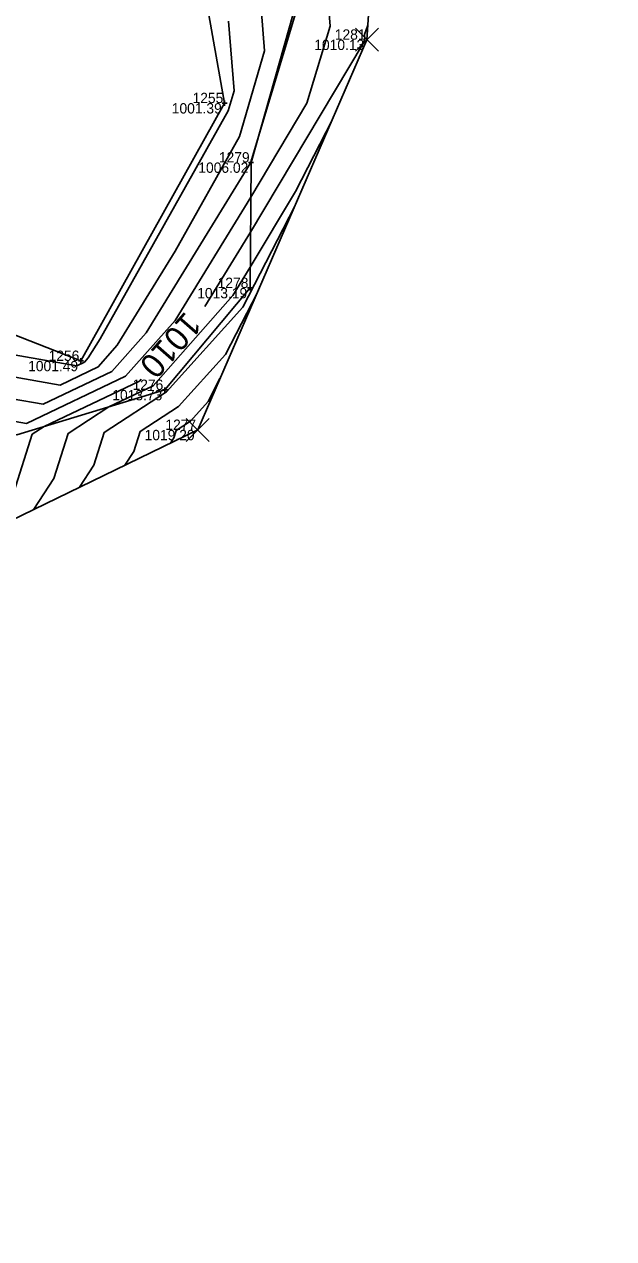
# Model space of a CAD drawing. Extents: x 2354693 to 2355622, y 637071 to 710080.
# Drawn here: x 2355546 to 2355614.4, y 709334.6 to 709475.6 of the extents above; entities that cross this region are included whole.
import ezdxf

# ---------------------------------------------------------------- set-up
doc = ezdxf.new("R2010")
doc.units = 0
for name, color, linetype in [('Default', 7, 'Continuous'), ('DT_X_Contour_Major', 7, 'Continuous'), ('DT_X_Contour_Minor', 7, 'Continuous'), ('HY_X_Water_Edge', 7, 'Continuous'), ('SV_X_Random_Point', 7, 'Continuous'), ('SV_X_Shot_Marker', 7, 'Continuous'), ('SV_X_Text_Elevation', 7, 'Continuous'), ('SV_X_Text_Name', 7, 'Continuous'), ('SV_X_Toe_of_Slope', 7, 'Continuous'), ('SV_X_Top_of_Bank', 7, 'Continuous')]:
    doc.layers.add(name, color=color, linetype=linetype)

msp = doc.modelspace()

# ---------------------------------------------------------------- linework, layer by layer
at = {"layer": 'Default'}
msp.add_lwpolyline([(2355263.76, 708986.4), (2355330.91, 709003.61), (2355347.35, 709002.09), (2355387.45, 709051.54), (2355402.1, 709089.16), (2355425.96, 709130.16), (2355495.56, 709194.41), (2355530.33, 709221.46), (2355525, 709302.12), (2355509.66, 709318.33), (2355534.8, 709413.26), (2355566.11, 709428.47), (2355585.74, 709473.78), (2355589.64, 709532.44), (2355608.23, 709591.27)], dxfattribs=at)
msp.add_lwpolyline([(2355263.76, 708986.4), (2355330.91, 709003.61), (2355347.35, 709002.09), (2355387.45, 709051.54), (2355402.1, 709089.16), (2355425.96, 709130.16), (2355495.56, 709194.41), (2355530.33, 709221.46), (2355525, 709302.12), (2355509.66, 709318.33), (2355534.8, 709413.26), (2355566.11, 709428.47), (2355585.74, 709473.78), (2355589.64, 709532.44), (2355608.23, 709591.27)], dxfattribs=at)
at = {"layer": 'DT_X_Contour_Major'}
for points in [[(2355585.85, 709475.47), (2355585.44, 709474.38), (2355585.48, 709473.88), (2355585.32, 709473.34), (2355572.23, 709451.44), (2355566.92, 709442.79)], [(2355585.85, 709475.47), (2355585.44, 709474.38), (2355585.48, 709473.88), (2355585.32, 709473.34), (2355572.23, 709451.44), (2355566.92, 709442.79)], [(2355559.54, 709434.37), (2355559.34, 709434.14), (2355548.29, 709428.87), (2355546.89, 709427.96), (2355544.8, 709421.25), (2355541.84, 709416.68)], [(2355559.54, 709434.37), (2355559.34, 709434.14), (2355548.29, 709428.87), (2355546.89, 709427.96), (2355544.8, 709421.25), (2355541.84, 709416.68)]]:
    msp.add_lwpolyline(points, dxfattribs=at)
at = {"layer": 'DT_X_Contour_Minor'}
for points in [[(2355587.59, 709501.58), (2355580.8, 709483.62), (2355581.46, 709475.35), (2355578.77, 709466.39), (2355572.26, 709455.5), (2355563.48, 709441.19), (2355557.75, 709434.69), (2355546.26, 709429.21), (2355544.93, 709429.44), (2355542.14, 709428.27), (2355540.54, 709420.87), (2355540.17, 709419.68), (2355536.57, 709414.12)], [(2355587.59, 709501.58), (2355580.8, 709483.62), (2355581.46, 709475.35), (2355578.77, 709466.39), (2355572.26, 709455.5), (2355563.48, 709441.19), (2355557.75, 709434.69), (2355546.26, 709429.21), (2355544.93, 709429.44), (2355542.14, 709428.27), (2355540.54, 709420.87), (2355540.17, 709419.68), (2355536.57, 709414.12)], [(2355571.68, 709500.25), (2355573.87, 709472.48), (2355570.96, 709462.53), (2355563.49, 709449.24), (2355556.77, 709438.3), (2355554.57, 709435.79), (2355550.14, 709433.68), (2355544.26, 709434.7)], [(2355571.68, 709500.25), (2355573.87, 709472.48), (2355570.96, 709462.53), (2355563.49, 709449.24), (2355556.77, 709438.3), (2355554.57, 709435.79), (2355550.14, 709433.68), (2355544.26, 709434.7)], [(2355577.44, 709476.81), (2355573.15, 709462.53), (2355572.28, 709459.56), (2355572.2, 709459.42), (2355560.12, 709439.74), (2355556.16, 709435.24), (2355548.2, 709431.44), (2355544.6, 709432.07)], [(2355577.44, 709476.81), (2355573.15, 709462.53), (2355572.28, 709459.56), (2355572.2, 709459.42), (2355560.12, 709439.74), (2355556.16, 709435.24), (2355548.2, 709431.44), (2355544.6, 709432.07)], [(2355569.68, 709475.93), (2355570.32, 709467.83), (2355569.64, 709465.5), (2355554.78, 709439.06), (2355553.42, 709436.85), (2355552.97, 709436.34), (2355552.08, 709435.92), (2355543.92, 709437.33)], [(2355569.68, 709475.93), (2355570.32, 709467.83), (2355569.64, 709465.5), (2355554.78, 709439.06), (2355553.42, 709436.85), (2355552.97, 709436.34), (2355552.08, 709435.92), (2355543.92, 709437.33)], [(2355581.69, 709464.43), (2355577.46, 709456.17), (2355572.2, 709447.37), (2355570.18, 709444.09), (2355560.93, 709433.59), (2355555.81, 709431.15), (2355551.07, 709428.07), (2355549.44, 709422.82), (2355547.12, 709419.25)], [(2355581.69, 709464.43), (2355577.46, 709456.17), (2355572.2, 709447.37), (2355570.18, 709444.09), (2355560.93, 709433.59), (2355555.81, 709431.15), (2355551.07, 709428.07), (2355549.44, 709422.82), (2355547.12, 709419.25)], [(2355577.36, 709454.44), (2355571.36, 709442.73), (2355562.5, 709432.88), (2355555.25, 709428.18), (2355554.07, 709424.39), (2355552.4, 709421.81)], [(2355577.36, 709454.44), (2355571.36, 709442.73), (2355562.5, 709432.88), (2355555.25, 709428.18), (2355554.07, 709424.39), (2355552.4, 709421.81)], [(2355573.03, 709444.44), (2355569.34, 709437.24), (2355563.89, 709431.18), (2355559.43, 709428.29), (2355558.7, 709425.96), (2355557.67, 709424.37)], [(2355573.03, 709444.44), (2355569.34, 709437.24), (2355563.89, 709431.18), (2355559.43, 709428.29), (2355558.7, 709425.96), (2355557.67, 709424.37)], [(2355568.69, 709434.45), (2355567.31, 709431.75), (2355565.27, 709429.48), (2355563.61, 709428.4), (2355563.34, 709427.53), (2355562.95, 709426.94)], [(2355568.69, 709434.45), (2355567.31, 709431.75), (2355565.27, 709429.48), (2355563.61, 709428.4), (2355563.34, 709427.53), (2355562.95, 709426.94)]]:
    msp.add_lwpolyline(points, dxfattribs=at)
at = {"layer": 'HY_X_Water_Edge'}
msp.add_lwpolyline([(2355601.98, 709641.84), (2355600.27, 709603.87), (2355587.93, 709575.67), (2355574.93, 709552.02), (2355564.16, 709527.42), (2355560.86, 709513.6), (2355569.23, 709466.41), (2355552.57, 709436.48), (2355543.58, 709440.01), (2355530.89, 709431.5), (2355507.81, 709418.76), (2355493.48, 709407.24), (2355475.84, 709401.85), (2355468.12, 709405.11), (2355452.68, 709393.73)], dxfattribs=at)
at = {"layer": 'SV_X_Random_Point'}
for p, q in [((2355584.41, 709472.45), (2355587.07, 709475.12)), ((2355584.41, 709475.12), (2355587.07, 709472.45)), ((2355564.77, 709427.13), (2355567.44, 709429.8)), ((2355564.77, 709429.8), (2355567.44, 709427.13))]:
    msp.add_line(p, q, dxfattribs=at)
at = {"layer": 'SV_X_Shot_Marker'}
for p, q in [((2355569.53, 709466.41), (2355568.93, 709466.41)), ((2355569.23, 709466.71), (2355569.23, 709466.11)), ((2355572.3, 709459.82), (2355572.3, 709459.22)), ((2355572.6, 709459.52), (2355572, 709459.52)), ((2355572.48, 709444.95), (2355571.88, 709444.95)), ((2355572.18, 709445.25), (2355572.18, 709444.65)), ((2355552.87, 709436.48), (2355552.27, 709436.48)), ((2355552.57, 709436.78), (2355552.57, 709436.18)), ((2355562.61, 709433.11), (2355562.01, 709433.11)), ((2355562.31, 709433.41), (2355562.31, 709432.81))]:
    msp.add_line(p, q, dxfattribs=at)
at = {"layer": 'SV_X_Toe_of_Slope'}
msp.add_lwpolyline([(2355601.98, 709641.84), (2355600.27, 709603.87), (2355587.93, 709575.67), (2355574.93, 709552.02), (2355564.16, 709527.42), (2355560.86, 709513.6), (2355569.23, 709466.41), (2355552.57, 709436.48), (2355543.58, 709440.01), (2355530.89, 709431.5), (2355507.81, 709418.76), (2355493.48, 709407.24), (2355475.84, 709401.85), (2355468.12, 709405.11), (2355452.68, 709393.73)], dxfattribs=at)
at = {"layer": 'SV_X_Top_of_Bank'}
msp.add_lwpolyline([(2355539.65, 709419.5), (2355536.88, 709428.91), (2355545.13, 709427.91), (2355562.31, 709433.11), (2355572.18, 709444.95), (2355572.3, 709459.52), (2355577.24, 709476.89), (2355570.97, 709503.21), (2355563.87, 709514.15), (2355574.03, 709537.88), (2355587.83, 709570.74), (2355601.3, 709594.65), (2355608.86, 709626.36), (2355614.36, 709652.49)], dxfattribs=at)

# ---------------------------------------------------------------- texts
at = {"layer": 'DT_X_Contour_Major'}
msp.add_text('1010', height=2.8, rotation=228.7766, dxfattribs=at).set_placement((2355564.68, 709442.34))
msp.add_text('1010', height=2.8, rotation=228.7766, dxfattribs=at).set_placement((2355564.68, 709442.34))
at = {"layer": 'SV_X_Text_Elevation'}
for s, p in [('1010.13', (2355579.63, 709472.58)), ('1001.39', (2355563.1, 709465.21)), ('1006.02', (2355566.18, 709458.32)), ('1013.19', (2355566.05, 709443.75)), ('1001.49', (2355546.44, 709435.28)), ('1013.73', (2355556.2, 709431.91)), ('1019.20', (2355559.95, 709427.27))]:
    msp.add_text(s, height=1.2, dxfattribs=at).set_placement(p)
at = {"layer": 'SV_X_Text_Name'}
for s, p in [('1281', (2355582.01, 709473.78)), ('1255', (2355565.51, 709466.41)), ('1279', (2355568.56, 709459.52)), ('1278', (2355568.42, 709444.95)), ('1256', (2355548.81, 709436.48)), ('1276', (2355558.55, 709433.11)), ('1277', (2355562.36, 709428.47))]:
    msp.add_text(s, height=1.2, dxfattribs=at).set_placement(p)

doc.saveas('drawing.dxf')
